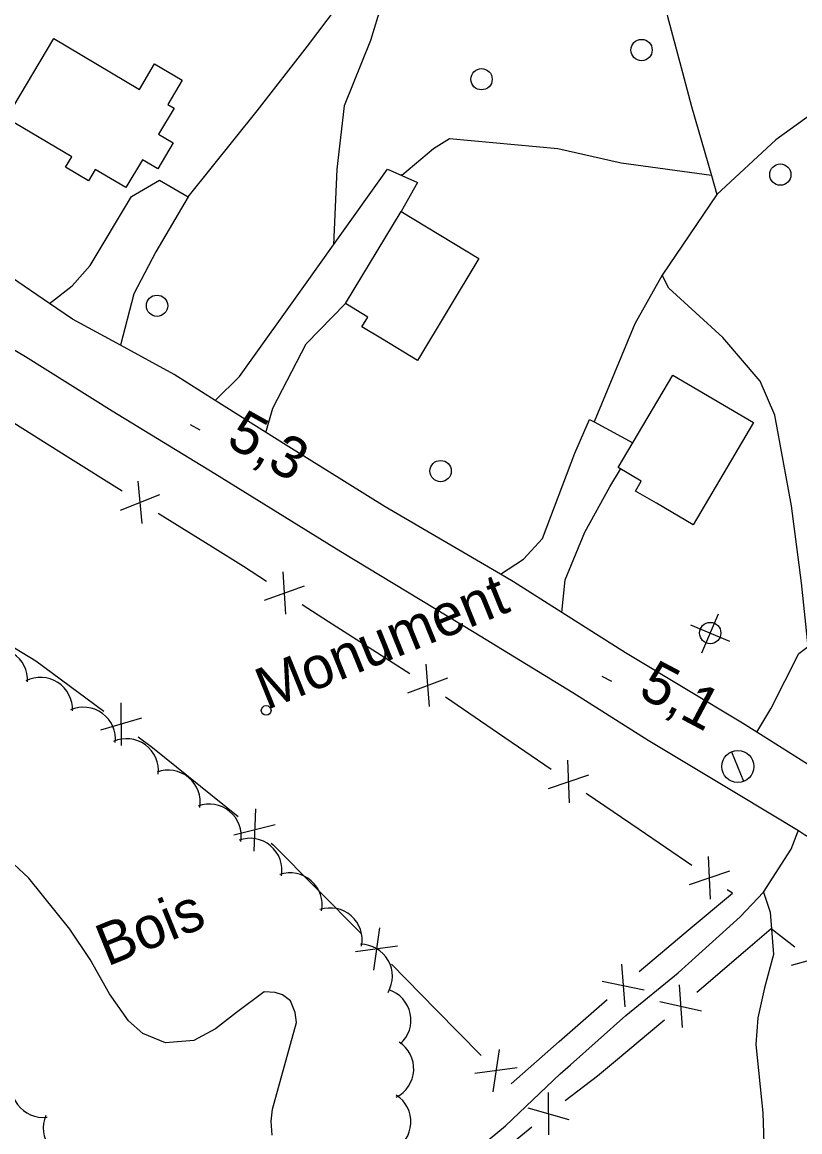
# Model space of a CAD drawing. Extents: x 362852 to 366875, y 5563573 to 5566479.
# Drawn here: x 363874.5 to 363947.4, y 5564712.5 to 5564816.7 of the extents above; entities that cross this region are included whole.
import ezdxf

# ---------------------------------------------------------------- set-up
doc = ezdxf.new("R2010")
doc.units = 0
for name, color, linetype in [('Niveau 19', 7, 'Continuous'), ('Niveau 2', 7, 'Continuous'), ('Niveau 21', 7, 'Continuous'), ('Niveau 22', 7, 'Continuous'), ('Niveau 3', 7, 'Continuous'), ('Niveau 31', 7, 'Continuous'), ('Niveau 36', 7, 'Continuous'), ('Niveau 37', 7, 'Continuous'), ('Niveau 39', 7, 'Continuous'), ('Niveau 44', 7, 'Continuous')]:
    doc.layers.add(name, color=color, linetype=linetype)

msp = doc.modelspace()

# ---------------------------------------------------------------- linework, layer by layer
at = {"layer": 'Niveau 19'}
for points in [[(363892.58, 5564781.17), (363894.86, 5564783.4), (363901.06, 5564792.08), (363903.68, 5564795.78), (363908.73, 5564802.89), (363910.07, 5564802.29), (363911.55, 5564801.61), (363910.02, 5564798.89)], [(363877.05, 5564790.27), (363879.16, 5564791.91), (363880.85, 5564793.84), (363884.72, 5564800.32), (363887.34, 5564801.83), (363890.05, 5564800.28), (363887, 5564795.11), (363884.95, 5564791.16), (363883.68, 5564786.36)], [(363897.32, 5564778.17), (363898, 5564780.45), (363901.11, 5564786.49), (363904.8, 5564790.25)], [(363919.34, 5564764.85), (363921.5, 5564766.27), (363923.28, 5564768.19), (363926.32, 5564776.21), (363927.7, 5564779.39), (363928.12, 5564779.16), (363931.74, 5564777.17)], [(363925.08, 5564761.27), (363925.42, 5564764.32), (363927.25, 5564768.81), (363929.6, 5564773.07), (363930.61, 5564774.72)], [(363943.37, 5564750.03), (363944.7, 5564752.22), (363947.31, 5564757.4), (363948.2, 5564758.07), (363949.93, 5564757.35), (363952.4, 5564761.03), (363953.61, 5564762.59), (363954.08, 5564762.22), (363956.55, 5564760.27)]]:
    msp.add_lwpolyline(points, dxfattribs=at)
at = {"layer": 'Niveau 2'}
msp.add_lwpolyline([(363897.93, 5564712.19), (363897.83, 5564713.51), (363897.94, 5564714.62), (363900.21, 5564722.78), (363900.07, 5564723.72), (363899.64, 5564724.79), (363898.9, 5564725.36), (363898.2, 5564725.57), (363897.17, 5564725.65), (363894.59, 5564723.72), (363892.61, 5564722.16), (363890.56, 5564721.07), (363887.91, 5564720.86), (363885.8, 5564721.74), (363884.44, 5564722.93), (363882.67, 5564725.45), (363880.84, 5564728.69), (363878.94, 5564731.53), (363875.11, 5564736.32), (363872.69, 5564738.57)], dxfattribs=at)
at = {"layer": 'Niveau 21'}
for points in [[(363879.19, 5564788.81), (363877.05, 5564790.27), (363871.66, 5564793.94)], [(363994.43, 5564711.91), (363983.6, 5564718.56), (363974.5, 5564723.93), (363966.81, 5564728.69), (363959.4, 5564733.25), (363951.03, 5564738.49), (363947.85, 5564740.4), (363947.28, 5564740.75), (363941.62, 5564744.16), (363933.18, 5564749.24), (363926.13, 5564753.7), (363916.88, 5564759.39), (363904.37, 5564766.96), (363892.54, 5564774.27), (363882.9, 5564780.17), (363874.78, 5564785.26), (363865.85, 5564790.51)], [(364013.59, 5564706.86), (364004.13, 5564712.95), (363998.16, 5564716.58), (363995.19, 5564718.39), (363985.17, 5564724.44), (363977.81, 5564728.9), (363968.57, 5564734.46), (363965.42, 5564736.38), (363959.7, 5564739.86), (363950.81, 5564745.32), (363947.55, 5564747.38), (363943.37, 5564750.03), (363942.04, 5564750.87), (363931.07, 5564757.47), (363925.08, 5564761.27), (363920.56, 5564764.14), (363919.34, 5564764.85), (363908.52, 5564771.17), (363899.24, 5564776.96), (363892.58, 5564781.17), (363888.72, 5564783.61), (363883.68, 5564786.36), (363879.19, 5564788.81)]]:
    msp.add_lwpolyline(points, dxfattribs=at)
at = {"layer": 'Niveau 22'}
for points in [[(363955.07, 5564870.77), (363951.94, 5564867.1), (363948.66, 5564861.82), (363946.28, 5564856.69), (363941.4, 5564850.64), (363937.88, 5564846.65), (363935.77, 5564844.9), (363932.27, 5564842.01), (363925.13, 5564836.65), (363919.01, 5564832.81), (363916.4, 5564830.69), (363912.85, 5564827.07), (363910.81, 5564824.31), (363907.84, 5564817.22), (363907.15, 5564814.95), (363904.68, 5564808.83), (363904, 5564802.89), (363903.68, 5564795.78)], [(363930.51, 5564830.95), (363931.91, 5564827.11), (363933.02, 5564823.23), (363934.38, 5564819.8), (363935.01, 5564817.2), (363936.28, 5564812.42), (363937.25, 5564808.75), (363939.12, 5564802.29), (363939.63, 5564800.51)], [(363890.05, 5564800.28), (363896.53, 5564808.36), (363901.23, 5564814.41), (363905.91, 5564820.63), (363909.09, 5564824.1), (363912.85, 5564827.07)], [(363977.85, 5564824.64), (363975.45, 5564822.6), (363967.6, 5564818.56), (363958.81, 5564814.74), (363956.28, 5564812.93), (363951.32, 5564810.08), (363945.18, 5564805.64), (363939.63, 5564800.51), (363934.52, 5564792.91), (363931.95, 5564788.37), (363928.12, 5564779.16)], [(363939.12, 5564802.29), (363930.65, 5564803.44), (363924.72, 5564804.77), (363914.55, 5564805.71), (363913.07, 5564804.8), (363910.07, 5564802.29), (363910.06, 5564802.37)], [(363948.2, 5564758.07), (363947.56, 5564764.04), (363946.65, 5564771.26), (363945.07, 5564779.79), (363943.71, 5564782.97), (363940.21, 5564787.08), (363935.12, 5564791.72), (363934.52, 5564792.91)], [(363915.69, 5564709.64), (363919.8, 5564713.06), (363924.94, 5564717.95), (363925.9, 5564718.78), (363931.11, 5564723.41), (363936, 5564727.42), (363941.83, 5564732.68), (363944, 5564735), (363946.61, 5564739.05), (363947.23, 5564740.67), (363947.28, 5564740.75)], [(363944, 5564735), (363944.64, 5564733.14), (363944.95, 5564729.16), (363944.11, 5564726.01), (363943.47, 5564723.19), (363943.3, 5564720.69), (363943.96, 5564714.29), (363944.11, 5564709.49), (363943.67, 5564706.33), (363942.34, 5564697.99), (363941.72, 5564693.26), (363941.45, 5564691.15), (363942.07, 5564683.19), (363943.72, 5564680.69)]]:
    msp.add_lwpolyline(points, dxfattribs=at)
at = {"layer": 'Niveau 3'}
for p, q in [((363890.22, 5564778.92), (363891.13, 5564778.41)), ((363928.84, 5564755.29), (363929.75, 5564754.8))]:
    msp.add_line(p, q, dxfattribs=at)
at = {"layer": 'Niveau 31'}
for points in [[(363877.43, 5564815.13), (363885.48, 5564810.36), (363886.9, 5564812.77), (363889.49, 5564811.24), (363888.14, 5564808.96), (363888.72, 5564808.61), (363887.27, 5564806.16), (363888.64, 5564805.35), (363887.19, 5564802.9), (363885.75, 5564803.76), (363884.2, 5564801.15), (363881.32, 5564802.85), (363880.69, 5564801.78), (363878.54, 5564803.05), (363879.13, 5564804.04), (363873.01, 5564807.66), (363877.43, 5564815.13)], [(363910.02, 5564798.89), (363917.32, 5564794.48), (363911.54, 5564784.92), (363908.26, 5564786.91), (363906.34, 5564788.07), (363906.89, 5564788.98), (363904.8, 5564790.25), (363910.02, 5564798.89)], [(363935.5, 5564783.54), (363943.07, 5564779.08), (363937.41, 5564769.48), (363933.96, 5564771.52), (363932.01, 5564772.66), (363932.55, 5564773.58), (363930.38, 5564774.86), (363935.5, 5564783.54)]]:
    msp.add_lwpolyline(points, dxfattribs=at)
at = {"layer": 'Niveau 36'}
for p, q in [((363938.24, 5564757.46), (363939.79, 5564761.13)), ((363940.85, 5564758.52), (363937.18, 5564760.07)), ((363942.16, 5564745.38), (363941.04, 5564748.16))]:
    msp.add_line(p, q, dxfattribs=at)
for centre, radius in [((363932.57, 5564814.06), 1), ((363917.56, 5564811.32), 1), ((363945.59, 5564802.37), 1), ((363887.12, 5564790.05), 1), ((363913.72, 5564774.53), 1), ((363939.01, 5564759.33), 1), ((363941.6, 5564746.8), 1.5)]:
    msp.add_circle(centre, radius, dxfattribs=at)
at = {"layer": 'Niveau 37'}
for p, q in [((363878.76, 5564775.85), (363873.68, 5564779.04)), ((363883.84, 5564772.66), (363878.76, 5564775.85)), ((363885.72, 5564769.61), (363885.36, 5564773.59)), ((363883.68, 5564770.87), (363887.4, 5564772.33)), ((363892.34, 5564767.39), (363887.23, 5564770.54)), ((363899.21, 5564761.09), (363898.95, 5564765.08)), ((363897.2, 5564762.4), (363900.96, 5564763.77)), ((363910.84, 5564755.49), (363905.79, 5564758.73)), ((363877.33, 5564755.56), (363882.14, 5564751.98)), ((363912.67, 5564752.42), (363912.38, 5564756.41)), ((363910.65, 5564753.71), (363914.4, 5564755.11)), ((363883.73, 5564752.78), (363883.75, 5564748.78)), ((363919.14, 5564749.91), (363914.19, 5564753.3)), ((363885.66, 5564751.35), (363881.82, 5564750.22)), ((363924.08, 5564746.51), (363919.14, 5564749.91)), ((363925.82, 5564743.38), (363925.65, 5564747.38)), ((363890.06, 5564745.87), (363894.72, 5564742.1)), ((363923.84, 5564744.74), (363927.63, 5564746.02)), ((363896.35, 5564742.84), (363896.2, 5564738.84)), ((363898.21, 5564741.33), (363894.34, 5564740.35)), ((363937.29, 5564737.49), (363932.34, 5564740.87)), ((363939.04, 5564734.36), (363938.86, 5564738.36)), ((363937.06, 5564735.72), (363940.85, 5564737.01)), ((363902.08, 5564735.35), (363906.31, 5564731.09)), ((363908, 5564731.65), (363907.42, 5564727.69)), ((363932.36, 5564727.56), (363936.95, 5564731.42)), ((363909.69, 5564729.94), (363905.73, 5564729.39)), ((363937.76, 5564725.62), (363942.31, 5564729.52)), ((363950.47, 5564729.18), (363946.61, 5564728.11)), ((363909.12, 5564728.24), (363913.32, 5564723.96)), ((363930.7, 5564728.24), (363931, 5564724.25)), ((363928.89, 5564726.65), (363932.81, 5564725.83)), ((363936.11, 5564726.3), (363936.37, 5564722.31)), ((363924.84, 5564720.97), (363929.35, 5564724.93)), ((363934.29, 5564724.74), (363938.19, 5564723.87)), ((363913.32, 5564723.96), (363917.52, 5564719.67)), ((363919.22, 5564720.22), (363918.61, 5564716.27)), ((363920.33, 5564717.01), (363924.84, 5564720.97)), ((363920.9, 5564718.51), (363916.93, 5564717.98)), ((363923.81, 5564716.21), (363923.85, 5564712.21)), ((363921.91, 5564714.75), (363925.76, 5564713.67)), ((363917.62, 5564709.17), (363922.28, 5564712.96))]:
    msp.add_line(p, q, dxfattribs=at)
for points in [[(363897.4, 5564764.18), (363895.24, 5564765.59), (363892.34, 5564767.39)], [(363905.79, 5564758.73), (363903.21, 5564760.38), (363900.75, 5564761.99)], [(363872.29, 5564758.81), (363875.76, 5564756.73), (363877.33, 5564755.56)], [(363885.35, 5564749.59), (363886.69, 5564748.59), (363890.06, 5564745.87)], [(363932.34, 5564740.87), (363927.47, 5564744.19), (363927.38, 5564744.25)], [(363897.84, 5564739.59), (363898.03, 5564739.43), (363902.08, 5564735.35)], [(363936.95, 5564731.42), (363941.09, 5564734.9), (363940.6, 5564735.23)], [(363942.31, 5564729.52), (363944.73, 5564731.59), (363946.96, 5564729.87)], [(363930.12, 5564719.16), (363934.58, 5564722.89), (363934.72, 5564723.01)], [(363925.42, 5564715.43), (363928.44, 5564717.75), (363930.12, 5564719.16)]]:
    msp.add_lwpolyline(points, dxfattribs=at)
at = {"layer": 'Niveau 39'}
msp.add_circle((363897.36, 5564752.06), 0.455, dxfattribs=at)
at = {"layer": 'Niveau 44'}
for centre, start, end in [((363871.99, 5564754.89), 357.1194, 117.0973), ((363876.19, 5564752.17), 357.1194, 117.0973), ((363880.22, 5564749.37), 353.7336, 113.7115), ((363884.25, 5564746.41), 353.7336, 113.7115), ((363888.17, 5564743.46), 350.349, 110.3269), ((363892.02, 5564740.27), 350.349, 110.3269), ((363895.84, 5564737.06), 349.8482, 109.8261), ((363899.61, 5564733.82), 348.814, 108.7919), ((363903.37, 5564730.52), 348.814, 108.7919), ((363906.2, 5564727.11), 329.6881, 89.666), ((363907.94, 5564722.98), 311.939, 71.917), ((363908.2, 5564718.42), 296.9345, 56.9125), ((363876.45, 5564716.86), 156.776, 276.7539), ((363907.93, 5564713.43), 296.9345, 56.9125), ((363879.45, 5564712.85), 156.776, 276.7539)]:
    msp.add_arc(centre, 3, start, end, dxfattribs=at)

# ---------------------------------------------------------------- texts
at = {"layer": 'Niveau 3'}
for s, rotation, p in [('5,3  ', 330.685, (363893.47, 5564777.02)), ('5,1  ', 331.9795, (363932.13, 5564753.47))]:
    msp.add_text(s, height=3.93, rotation=rotation, dxfattribs=at).set_placement(p)
at = {"layer": 'Niveau 39'}
msp.add_text('Monument', height=3.93, rotation=22.09, dxfattribs=at).set_placement((363897.41, 5564752.08))
at = {"layer": 'Niveau 44'}
msp.add_text('Bois', height=3.93, rotation=22.09, dxfattribs=at).set_placement((363882.45, 5564728))

doc.saveas('drawing.dxf')
